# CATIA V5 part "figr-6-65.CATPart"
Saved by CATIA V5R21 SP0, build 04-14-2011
Part number: Part2
Bounding box of the stored display mesh (mm): x -31.464 to 31.464, y -26.321 to 36.69, z 59.463 to 122.391
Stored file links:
  D:\CATIA V5R21 E-RESOURCES\CATIA-V5R21\catia-v5r21-prt\c06-catia-v5r21-prt\c06-catia-v5r21-figr-6-65.CATPart
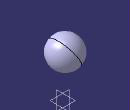
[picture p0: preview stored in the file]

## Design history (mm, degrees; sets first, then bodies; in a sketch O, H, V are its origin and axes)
Body1 (main body)
  Sketch1 on yz-plane, origin (0, 0, 0), H (0, 1, 0), V (0, 0, 1)
    axis line L1 (-55.8323, 90.9269) -> (61.0167, 90.9269)
    arc A1 centre (5.1844, 90.9269) radius 31.5054 from (36.6898, 90.9269) to (-26.3209, 90.9269) ccw
    point P3 (5.1844, 90.9269)
    point P4 (36.6898, 90.9269)
    point P5 (-26.3209, 90.9269)
    line L2 (-26.3209, 90.9269) -> (36.6898, 90.9269)
    horizontal: L1 H, L2 H
    coincidence: P3 L1, P4 L1, P5 L1
  Shaft1: profile Sketch1, axis Sketch1.L1, angle 360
